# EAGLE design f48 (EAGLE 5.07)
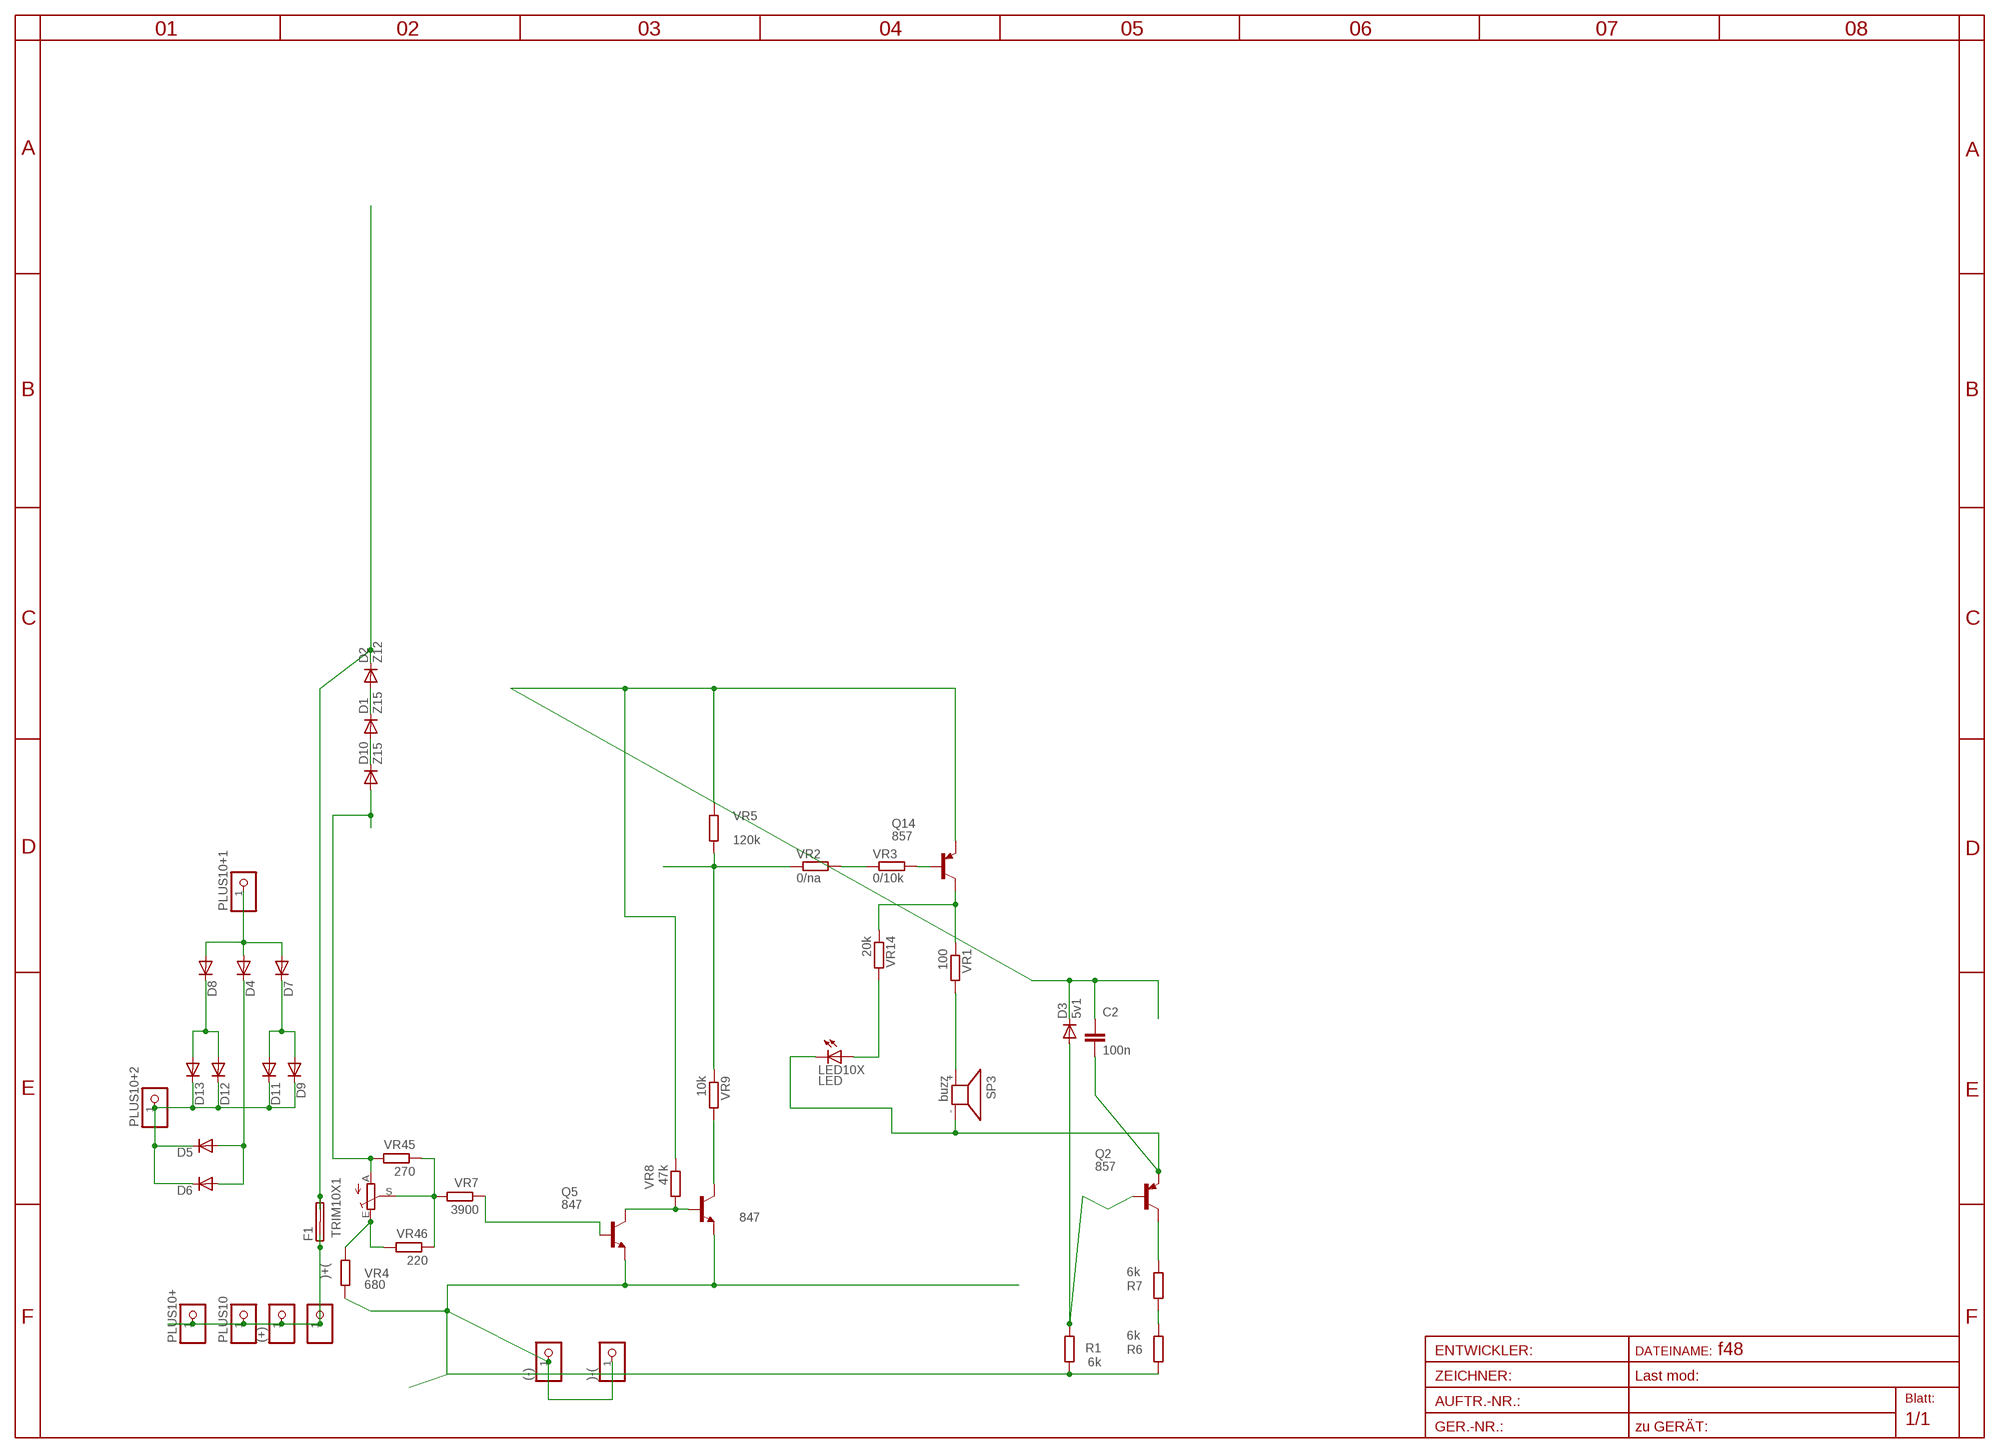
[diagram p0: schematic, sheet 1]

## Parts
(+)  PINHD-1X14.5MM  [1X4MM5]
(-)  PINHD-1X14.5MM  [1X4MM5]
)+(  PINHD-1X11X0.4  [1X01]
)-(  PINHD-1X11X0.4  [1X01]
C2  100n  C-EUC0805  [C0805]
D1  Z15  DIODE-MINIMELF  [MINIMELF]
D2  Z12  DIODE-MINIMELF  [MINIMELF]
D3  5v1  DIODE-MINIMELF  [MINIMELF]
D4  DIODE-SMC  [SMC]
D5  DIODE-SMC  [SMC]
D6  DIODE-SMC  [SMC]
D7  DIODE-SMC  [SMC]
D8  DIODE-SMC  [SMC]
D9  DIODE-SMC  [SMC]
D10  Z15  DIODE-MINIMELF  [MINIMELF]
D11  DIODE-SMC  [SMC]
D12  DIODE-SMC  [SMC]
D13  DIODE-SMC  [SMC]
F1  SHK20L7MM5  [7MM5]
LED10X  LED  LEDCHIPLED_1206  [CHIPLED_1206]
PLUS10  PINHD-1X14.5MM  [1X4MM5]
PLUS10+  PINHD-1X11X0.4  [1X01]
PLUS10+1  PINHD-1X11X0.4  [1X01]
PLUS10+2  PINHD-1X11X0.4  [1X01]
Q2  857  BC857CSMD  [SOT23-BEC]
Q5  847  BC847CSMD  [SOT23]
Q6  847  BC847CSMD  [SOT23]
Q14  857  BC857CSMD  [SOT23-BEC]
R1  6k  R-EU_R0805  [R0805]
R6  6k  R-EU_R0805  [R0805]
R7  6k  R-EU_R0805  [R0805]
SP3  buzz  KSS12017MM  [KSS1202]
TRIM10X1  TRIM_EU-S64W  [S64W]
VR1  100  R-EU_R0805  [R0805]
VR2  0/na  R-EU_R0805  [R0805]
VR3  0/10k  R-EU_R1206  [R1206]
VR4  680  R-EU_R0805  [R0805]
VR5  120k  R-EU_R0805  [R0805]
VR7  3900  R-EU_R1206  [R1206]
VR8  47k  R-EU_R1206  [R1206]
VR9  10k  R-EU_R0805  [R0805]
VR14  20k  R-EU_R0805  [R0805]
VR45  270  R-EU_R0805  [R0805]
VR46  220  R-EU_R1206  [R1206]

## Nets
BUZZ+: SP3.+ VR1.2
FPLUS: D2.C F1.2A F1.2B
INPLUS: (+).1 )+(.1 F1.1A F1.1B PLUS10+.1 PLUS10.1
LEDA: LED10X.A VR14.2
N$1: D1.C D2.A
N$2: VR2.2 VR3.1
N$3: Q5.3(C) Q6.1(B) VR8.2
N$4: D1.A D10.C
N$5: Q6.3(C) VR9.2
N$6: VR2.1 VR5.2 VR9.1
N$7: D7.C D9.A D11.A
N$8: Q14.C VR1.1 VR14.1
N$9: D4.A D7.A D8.A PLUS10+1.1
N$10: Q14.B VR3.2
N$11: D4.C D5.A D6.A
N$12: D5.C D6.C D9.C D11.C D12.C D13.C PLUS10+2.1
N$13: C2.1 D3.C Q14.E VR5.1 VR8.1
N$14: D8.C D12.A D13.A
N$15: D3.A Q2.B R1.2
N$16: Q2.C R7.1
N$17: D10.A TRIM10X1.A VR45.2
N$18: R6.1 R7.2
N$22: TRIM10X1.S VR7.2 VR45.1 VR46.1
N$24: TRIM10X1.E VR4.1 VR46.2
N$168: Q5.1(B) VR7.1
VSS: (-).1 )-(.1 Q5.2(E) Q6.2(E) R1.1 R6.2 VR4.2
VSS1: C2.2 LED10X.C Q2.E SP3.-

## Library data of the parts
(+) (-) )+( )-( PLUS10 PLUS10+ PLUS10+1 PLUS10+2 = pinhead:PINHD-1X1: PIN HEADER
C2 = rcl:C-EU: CAPACITOR, European symbol
D1-D13 = diode:DIODE-: DIODE
F1 = fuse:SHK20L: FUSE HOLDER 5 x 20 mm, SH contact, SHH1 Schukat, E1073 Buerklin
LED10X = led:LED: LED
Q2 Q14 = transistor-pnp:BC857*: PNP Transistror
Q5 Q6 = transistor-npn:BC847*: NPN Transistor
R1 R6 R7 VR1-VR5 VR7-VR9 VR14 VR45 VR46 = rcl-2:R-EU_: RESISTOR, European symbol
SP3 = buzzer:KSS1201: SPEAKER
TRIM10X1 = pot:TRIM_EU-: POTENTIOMETER

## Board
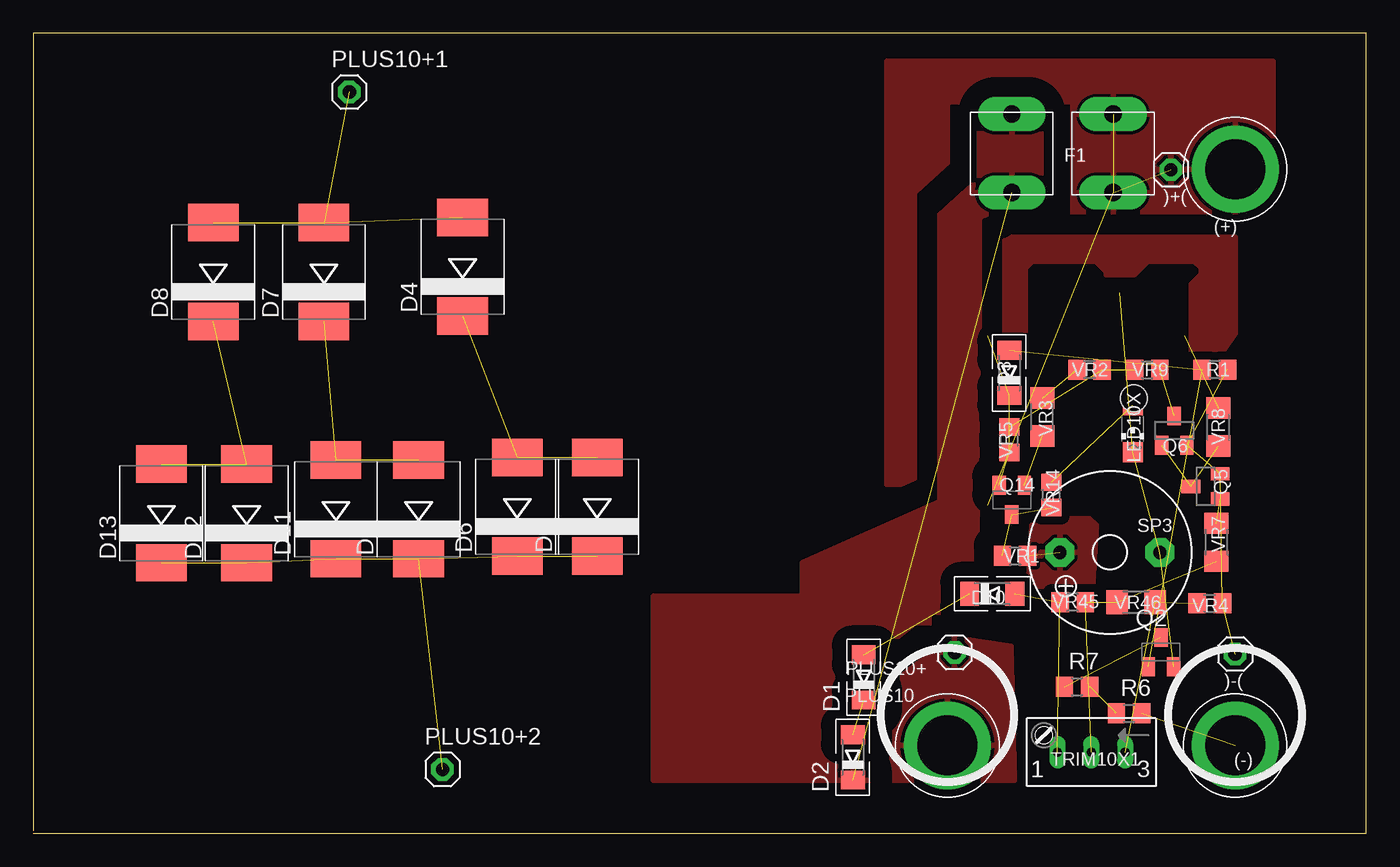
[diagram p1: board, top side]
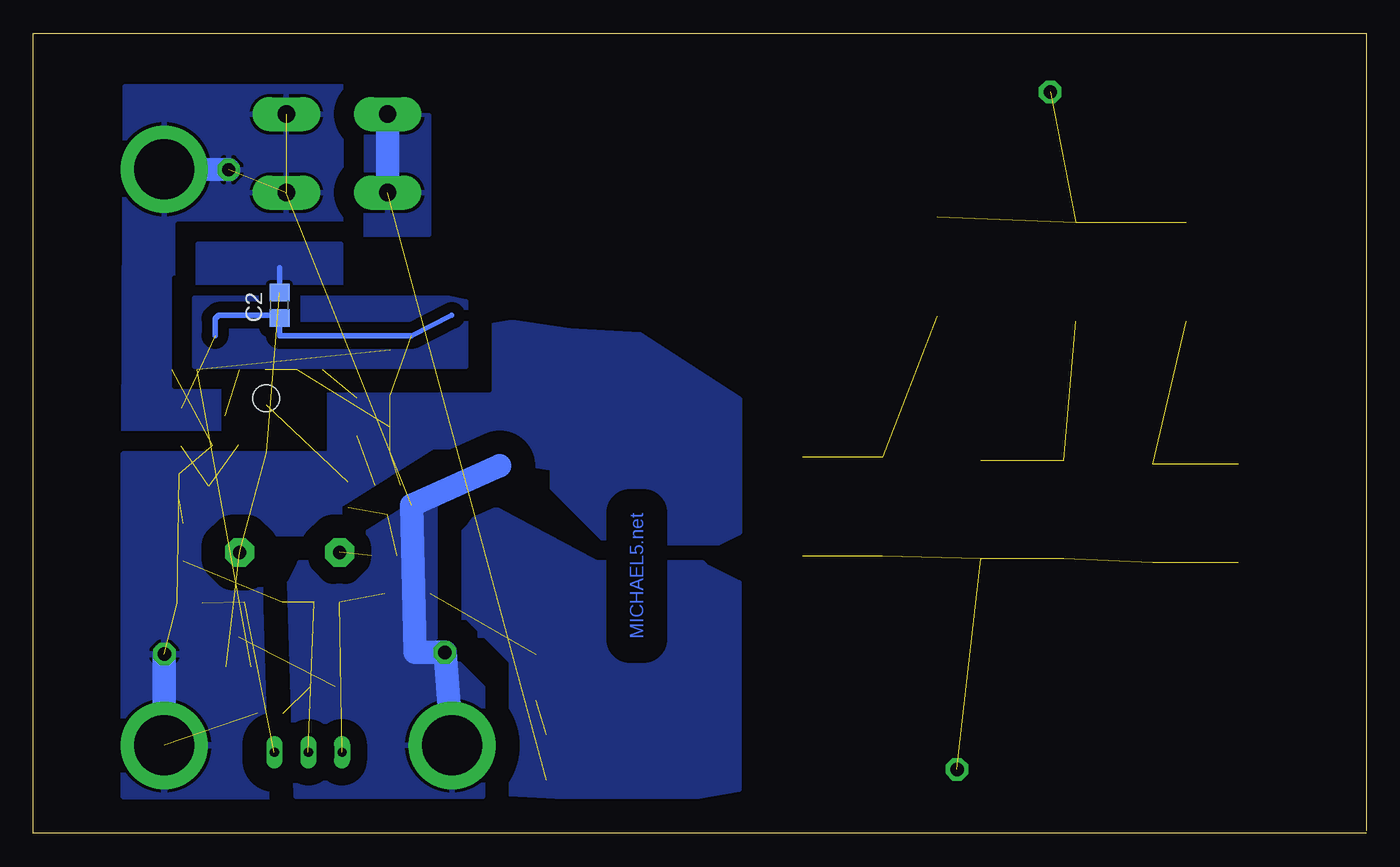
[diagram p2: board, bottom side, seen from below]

Size 100 x 60 mm. Coordinates in mm from the lower left corner, seen from the top.
Outline: 0,0 100,0 100,60 0,60 0,0.2
Copper layers (1*16): Top 0.035mm / dielectric 1.5mm / Bottom 0.035mm
Design rules "default *": minimum track width 8mil, minimum drill 4mil, track to track 8mil, track to pad 8mil, pad to pad 8mil, via to via 8mil, smd to smd 8mil, copper to edge 40mil, drill to drill 8mil, minimum pad ring 10mil, minimum via ring 8mil, stop-mask expansion 4mil, vias tented up to drill 0mil, thermal gap 10mil
Holes 2 mm at 82.55,32.64

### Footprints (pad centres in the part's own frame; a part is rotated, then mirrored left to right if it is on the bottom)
1X4MM5 = drill 4.5 pad 6.35 round: 1 0,0
1X01 = drill 1 pad 1.676 octagon: 1 0,0
C0805 = smd 1.3 x 1.5: 1 -0.95,0; 2 0.95,0
MINIMELF = smd 1.4 x 1.8: A 1.7,0; C -1.7,0
SMC = smd 2.8 x 3.8: A 3.7,0; C -3.7,0
7MM5 = drill 1.3 pad 2.54 long: 1A -3.8,2.94; 1B -3.8,-2.94; 2A 3.8,2.94; 2B 3.8,-2.94
CHIPLED_1206 = smd 1.5 x 1.5: A 0,-1.75; C 0,1.75
SOT23-BEC = smd 1 x 1.4: B -0.95,-1.1; C 0,1.1; E 0.95,-1.1
SOT23 = smd 1 x 1.4: 1 -0.95,-1.1; 2 0.95,-1.1; 3 0,1.1
R0805 = smd 1.3 x 1.5: 1 -0.95,0; 2 0.95,0
KSS1202 = drill 1 pad 2.159 octagon: + 3.75,0; - -3.75,0
S64W = drill 0.7 long: A 2.54,1.27; E -2.54,1.27; S 0,1.27
R1206 = smd 1.6 x 1.803: 1 -1.422,0; 2 1.422,0

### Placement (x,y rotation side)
(+)  90.17,49.8 0 top
(-)  90.17,6.59 0 top
)+(  85.34,49.77 0 top
)-(  90.17,13.45 0 top
C2  81.53,39.61 90 bottom
D1  62.3,11.7 90 top
D2  61.48,5.7 90 top
D3  73.22,34.53 90 top
D4  32.2,42.5 90 top
D5  42.3,24.5 90 top
D6  36.3,24.5 90 top
D7  21.8,42.1 90 top
D8  13.5,42.1 90 top
D9  28.9,24.3 90 top
D10  71.95,17.96 0 top
D11  22.7,24.3 90 top
D12  16,24 90 top
D13  9.6,24 90 top
F1  77.22,51 180 top
LED10X  82.49,30.34 180 top
PLUS10  68.58,6.59 0 top
PLUS10+  69.12,13.57 0 top
PLUS10+1  23.7,55.6 0 top
PLUS10+2  30.7,4.8 0 top
Q2  84.6,13.6 0 top
Q5  87.95,26.02 90 top
Q6  85.6,30.21 0 top
Q14  73.41,25 180 top
R1  88.65,34.78 180 top
R6  82.2,9 0 top
R7  78.3,11 0 top
SP3  80.77,21.07 180 top
TRIM10X1  79.38,7.35 180 top
VR1  73.66,20.81 0 top
VR2  79.25,34.78 180 top
VR3  75.69,31.23 270 top
VR4  88.27,17.26 0 top
VR5  73.22,29.51 90 top
VR7  88.77,21.83 270 top
VR8  88.9,30.47 270 top
VR9  83.57,34.78 0 top
VR14  76.39,25.39 90 top
VR45  77.98,17.32 180 top
VR46  82.74,17.32 0 top

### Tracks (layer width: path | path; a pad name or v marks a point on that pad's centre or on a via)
BUZZ+  (1 unrouted)
  pour Top (isolate 0.61): 75.69,23.61 79.25,23.61 79.76,23.1 79.5,18.78 79.25,18.53 75.44,18.53 74.68,19.29 74.93,23.1
FPLUS  (1 unrouted)
  Bottom 1.778: F1.2A F1.2B
  pour Bottom (isolate 1.778, rank 2): 60.77,2.78 50.1,2.78 47.05,3.29 47.05,18.78 49.59,20.05 49.85,20.31 57.72,20.31 66.29,24.88 68.58,24.88 69.6,23.86 69.6,14.46 65.79,10.65 65.79,3.03
  pour Top (isolate 1.5, rank 2): 60.77,4 46.55,4 46.55,17.77 57.72,17.77 57.72,20.31 68,24.88 68,46.4 71.63,49.66 70.62,17.07 62.49,11.35 62.69,3.93
  pour Bottom (isolate 0.813): 67.56,35.04 67.56,39.86 68.83,40.12 87.88,40.12 87.88,35.04
  pour Top (isolate 2, rank 4): 70.36,53.83 76.45,53.83 76.45,44.94 70.36,44.94
  pour Bottom (isolate 1.5, rank 4): 70.36,53.83 76.45,53.83 76.45,44.94 70.36,44.94
INPLUS  (3 unrouted)
  Bottom 1.778: PLUS10.1 PLUS10+.1 71.37,13.57 71.63,24.62 65.02,27.56 | )+(.1 (+).1
  pour Bottom (isolate 1.27): 68.07,26.91 74.93,22.59 76.71,20.31 80.01,20.31 80.77,18.78 80.26,2.78 66.29,2.78 66.29,10.91 69.85,14.46 69.85,24.62 69.34,25.13
  pour Bottom (isolate 1.5, rank 3): 93.12,56 93.22,29.2 86.11,29.2 86.11,35.04 87.88,35.04 88.39,35.8 88.39,45.45 76.96,45.2 76.86,56
  pour Top (isolate 2): 73.35,14.04 73.6,4 63.89,4 63.89,10.81 68.83,14.7
  pour Top (isolate 1.5, rank 3): 64.04,57.9 93,57.9 93,45.71 77.98,45.71 77.98,54.85 68.58,54.85 68.58,47.74 69.09,26.18 64.04,26.18
LEDA  (1 unrouted)
N$1  (1 unrouted)
N$2  (1 unrouted)
N$3  (2 unrouted)
N$4  (1 unrouted)
N$5  (1 unrouted)
N$6  (2 unrouted)
N$7  (2 unrouted)
N$8  (2 unrouted)
N$9  (3 unrouted)
N$10  (1 unrouted)
N$11  (2 unrouted)
N$12  (6 unrouted)
N$13  (4 unrouted)
  Bottom 0.406: 86.36,37.32 86.36,38.59 86.11,38.85 81.53,38.85 C2.1 81.53,37.32 78.99,37.32 71.63,37.32 68.61,38.85
  Bottom 0.61: C2.1 81.66,38.66
N$14  (2 unrouted)
N$15  (2 unrouted)
N$16  (1 unrouted)
N$17  (2 unrouted)
N$18  (1 unrouted)
N$22  (3 unrouted)
N$24  (2 unrouted)
N$168  (1 unrouted)
VSS  (5 unrouted)
  Bottom 1.778: (-).1 )-(.1
  pour Top (isolate 0.61): 81.79,29.2 81.79,27.16 80.77,26.15 80.77,24.37 84.84,20.31 90.42,20.31 90.68,20.56 90.68,23.1 89.92,23.86 87.38,23.86 87.38,26.66 85.85,27.42
  pour Bottom (isolate 1.778, rank 2): 93.22,2.78 93.22,28.43 77.72,28.43 77.72,36.05 64.07,38.31 59.79,37.64 54.48,37.34 47.05,32.55 47.05,22.59 48.58,21.83 56.96,21.83 61.02,25.89 61.02,27.42 65.79,28.18 68.07,28.18 77.22,20.81 81.79,19.8 81.28,2.78
VSS1  (3 unrouted)
  Bottom 0.406: C2.2 81.53,42.4
  pour Top (isolate 0.61): 72.9,36.82 72.9,44.44 73.41,44.69 90.17,44.69 90.17,37.51 88.65,35.29 86.87,35.29 86.87,41.13 87.63,41.9 87.63,42.4 87.12,42.91 83.57,42.91 82.55,41.9 80.52,41.9 80.52,42.15 79.76,42.91 74.93,42.91 74.42,42.4 74.42,36.56
  pour Bottom (isolate 0.813, rank 2): 76.96,44.18 87.63,44.18 87.63,40.88 76.96,40.88

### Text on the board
Bottom: MICHAEL5.net
tTest: 4v4
Document: 1m | 10u | 10u | 300u | 2mA | 500u | 1m | 2m | 300u | 300u | 30u | 5m | 14m | 12m | 500u | 5m | 5m | 5m | 5m | 5m | 5m | 40m | 40m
